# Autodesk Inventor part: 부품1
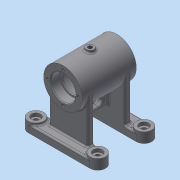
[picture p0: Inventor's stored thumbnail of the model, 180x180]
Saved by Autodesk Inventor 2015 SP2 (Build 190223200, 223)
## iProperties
Created: 2015-11
Part Number: 부품1
Material: 일반
Document SubType Name: Modeling
Designer: AMC
Density: 1 g/cm^3
Appearance: 기본값
Author: AMC
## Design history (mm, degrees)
sketch "스케치1"
  geometry: C1 r 25 at (0, 0); 1 further point
  constraints: 1 centre point, 1 coincident
  dimensions: "d0" = 50 diameter of C1
extrude "돌출1" new body sketch "스케치1" distance "d1" = 70; taper "d2" = 0 deg
sketch "스케치2"
  geometry: C1 r 5 at (0, 35); 1 further point
  constraints: 1 centre point
  dimensions: "d3" = 35 distance of point (0, 0) C1.centre; "d4" = 10 diameter of C1
extrude "돌출2" join sketch "스케치2" distance "d5" = 28; taper "d6" = 0 deg
sketch "스케치3"
  geometry: L1 (25, 70)-(-25, 70) reference; L2 (-25, 0)-(25, 0) reference; L3 (16, 70)-(16, 58); L4 (16, 58)-(14, 58); L5 (14, 58)-(14, 56); L6 (14, 56)-(21, 56); L7 (21, 56)-(21, 14); L8 (21, 14)-(14, 14); L9 (14, 14)-(14, 12); L10 (14, 12)-(16, 12); L11 (16, 12)-(16, 0); L12 (0, 70)-(0, 0)
  constraints: 20 end point, 8 perpendicular, 4 point on line, 1 midpoint, 1 vertical
  dimensions: "d7" = 32 diameter of L3 L12; "d8" = 28 diameter of L5 L12; "d9" = 42 diameter of L7 L12; "d10" = 32 diameter of L11 L12; "d11" = 42 distance of L6.end L7.end; "d12" = 12 distance of L3.start L3.end; "d13" = 12 distance of L10.end L11.end; "d120" = 2 distance of L8.end L9.end
revolve "회전1" sketch "스케치3" stored, may be unused: angle "d14" = 90 deg
sketch "스케치4"
  geometry: 2 further points
hole "구멍1" sketch "스케치4" at (0, 0) diameter "d15" = 5.188; stored, may be unused: countersink angle "d19" = 90 deg, drill point angle "d21" = 118 deg; dims "d16" = 25, "d17" = 4, "d18" = 2, "d20" = 29
node "작업 평면3"
sketch "스케치5"
  geometry: L1 (40, 75)-(-40, 75); L2 (-40, -5)-(40, -5); L3 (40, 55)-(4, 55); L4 (4, 55)-(4, 15); L5 (4, 15)-(40, 15); L6 (-4, 55)-(-40, 55); L7 (-40, 15)-(-4, 15); L8 (-4, 15)-(-4, 55); L9 (40, -5)-(40, 15); L10 (40, 55)-(40, 75); L11 (-40, 75)-(-40, 55); L12 (-40, 15)-(-40, -5); L13 (25, 70)-(-25, 70) reference; L14 (25, 0)-(25, 70) reference; L15 (-25, 0)-(25, 0) reference; L16 (-25, 0)-(-25, 70) reference; L17 (0, 70)-(0, 0); L18 (25, 35)-(-25, 35)
  constraints: 28 end point, 7 parallel, 4 midpoint, 3 horizontal, 3 perpendicular
  dimensions: "d37" = 80 distance of L2.end L1.start; "d38" = 80 distance of L1.start L1.end; "d39" = 20 distance between parallel lines of L1 L3; "d40" = 20 distance between parallel lines of L2 L5; "d43" = 20 distance between parallel lines of L2 L7; "d44" = 20 distance between parallel lines of L1 L6; "d47" = 36 distance of L6.start L6.end; "d48" = 36 distance of L3.start L3.end; "d49" = 36 distance of L7.start L7.end; "d50" = 0 distance between parallel lines of L11 L12; "d51" = 40 distance between parallel lines of L10 L17; "d52" = 40 distance between parallel lines of L1 L18
extrude "돌출3" join sketch "스케치5" distance "d53" = 10; taper "d54" = 0 deg
sketch "스케치6"
  geometry: 2 further points
  dimensions: "d55" = 20 distance of point (0, 20) point (0, 0); "d56" = 0 horizontal distance of point (0, 20) point (0, 0)
hole "구멍2" sketch "스케치6" at (0, 20) diameter "d57" = 3.242; stored, may be unused: countersink angle "d61" = 90 deg, drill point angle "d63" = 118 deg; dims "d58" = 8, "d59" = 4, "d60" = 2, "d62" = 10
sketch "스케치7"
  geometry: 2 further points
  dimensions: "d67" = 0 horizontal distance of point (0, 0) point (0, 20); "d68" = 20 distance of point (0, 20) point (0, 0)
hole "구멍3" sketch "스케치7" at (0, 20) diameter "d69" = 3.242; stored, may be unused: countersink angle "d73" = 90 deg, drill point angle "d75" = 118 deg; dims "d70" = 8, "d71" = 4, "d72" = 2, "d74" = 10
sketch "스케치8"
  geometry: L1 (-40, -5)-(-40, 15) reference; L2 (-40, 55)-(-40, 75) reference; L3 (40, 75)-(40, 55) reference; L4 (40, 15)-(40, -5) reference; 5 further points
  constraints: 4 midpoint, 4 vertical alignment, 8 other
extrude "돌출4" join sketch "스케치8" distance "d79" = 13; taper "d80" = 0 deg
sketch "스케치9"
  geometry: L1 (-80, -10)-(0, -10) reference; L2 (-44, 10)-(-80, 10) reference; L3 (-44, 50)-(-44, 10) reference; L4 (-80, 50)-(-44, 50) reference; L5 (0, 70)-(-80, 70) reference; L6 (-36, 50)-(0, 50) reference; L7 (-36, 10)-(-36, 50) reference; L8 (0, 10)-(-36, 10) reference; A1 r 10 centre (-80, 0) between (-80, 10) and (-80, -10) reference; A2 r 10 centre (-80, 60) between (-80, 70) and (-80, 50) reference; A3 r 10 centre (0, 60) between (0, 50) and (0, 70) reference; A4 r 10 centre (0, 0) between (0, -10) and (0, 10) reference; 2 further points
  constraints: 1 coincident
hole "구멍4" sketch "스케치9" at (0, 0) diameter "d81" = 6; stored, may be unused: countersink angle "d85" = 90 deg, drill point angle "d87" = 118 deg; dims "d82" = 8, "d83" = 12, "d84" = 4, "d86" = 30
sketch "스케치10"
  geometry: L1 (-25, -63)-(25, -63); L2 (-4, -55)-(-40, -55) reference; L3 (-25, -55)-(-0.273, -55); L4 (-0.273, -55)-(25, -55); L5 (-25, -55)-(-25, -63); L6 (25, -63)-(25, -55); L7 (-25, -15)-(25, -15); L8 (25, -15)-(25, -7); L9 (25, -7)-(-25, -7); L10 (-25, -7)-(-25, -15); L11 (-40, -15)-(-4, -15) reference; L12 (-40, -75)-(40, -75) reference; L13 (40, 5)-(-40, 5) reference; L14 (0, -75)-(0, 5); 1 further point
  constraints: 20 end point, 4 horizontal, 3 parallel, 2 midpoint, 2 perpendicular
  dimensions: "d94" = 8 distance between parallel lines of L1 L2; "d99" = 8 distance between parallel lines of L11 L9; "d100" = 50 distance of L1.start L1.end; "d101" = 50 distance of L8.end L9.end; "d102" = 25 distance between parallel lines of L5 L14; "d103" = 25 distance between parallel lines of L10 L14
extrude "돌출5" join sketch "스케치10" stored distance "d104" = 13; taper "d105" = 0 deg
sketch "스케치11"
  geometry: L1 (55, 43)-(-15, 43) reference; L2 (0, 10)-(0, 68) reference; L3 (40, 10)-(40, 68) reference; L4 (0, 23)-(40, 23); L5 (0, 43)-(40, 43); L6 (40, 43)-(40, 23); L7 (40, 23)-(0, 23); L8 (0, 23)-(0, 43); 1 further point
  constraints: 10 end point, 4 point on line, 2 parallel, 2 perpendicular, 1 horizontal
  dimensions: "d106" = 20 distance between parallel lines of L4 L1
extrude "돌출6" join sketch "스케치11" distance "d107" = 8; taper "d108" = 0 deg
sketch "스케치12"
  geometry: L1 (40, 10)-(0, 10) reference; L2 (-36, 0)-(76, 0) reference; L3 (0, 10)-(0, 68) reference; L4 (40, 10)-(40, 68) reference; L5 (0, 10)-(40, 10); L6 (40, 10)-(40, -24.732); L7 (40, -24.732)-(0, -24.732); L8 (0, -24.732)-(0, 10); 1 further point
  constraints: 8 end point, 2 parallel, 1 horizontal, 1 perpendicular
  dimensions: "d109" = 0 distance between parallel lines of L4 L6
extrude "돌출7" cut sketch "스케치12" distance "d110" = 10; taper "d111" = 0 deg
sketch "스케치13"
  geometry: L1 (13.043, 33)-(26.957, 33); L2 (13.043, 28.457)-(26.957, 28.457); L3 (26.957, 37.543)-(13.043, 37.543); L4 (-20, 0)-(-20, 10) reference; L5 (53, 0)-(47, 0) reference; A1 r 4.543 centre (13.043, 33) between (13.043, 37.543) and (13.043, 28.457); A2 r 4.543 centre (26.957, 33) between (26.957, 28.457) and (26.957, 37.543); 2 further points
  constraints: 8 end point, 4 point on circle, 4 tangent, 2 centre point, 1 horizontal, 1 midpoint, 1 parallel
  dimensions: "d113" = 40 distance from line of L4 point (20, 33); "d114" = 33 distance from line of L5 point (20, 33)
extrude "돌출8" cut sketch "스케치13" distance "d115" = 20; taper "d116" = 0 deg
fillet "모깎기1" dims "d117" = 3.5
fillet "모깎기2" dims "d118" = 0.3
fillet "모깎기4" dims "d121" = 0.3
fillet "모깎기5" dims "d122" = 3
fillet "모깎기6" dims "d123" = 2
fillet "모깎기7" dims "d124" = 2
fillet "모깎기8" dims "d125" = 2
fillet "모깎기9" dims "d126" = 2
fillet "모깎기10" dims "d129" = 2
chamfer "모따기1" distance "d130" = 1; stored, may be unused: second distance "d131" = 2, angle "d132" = 45 deg
chamfer "모따기2" distance "d133" = 1; stored, may be unused: second distance "d134" = 2, angle "d135" = 45 deg
node "솔리드1"
pattern_circular "원형 패턴1" dims angle "d65" = 360 deg
pattern_circular "원형 패턴2" dims angle "d77" = 360 deg
pattern_linear "직사각형 패턴1" dims "d90" = 80
pattern_linear "직사각형 패턴2"
node "투영된 루프1"
other parameters: "d24" = -68, "d33" = 32, "d41" = 32
